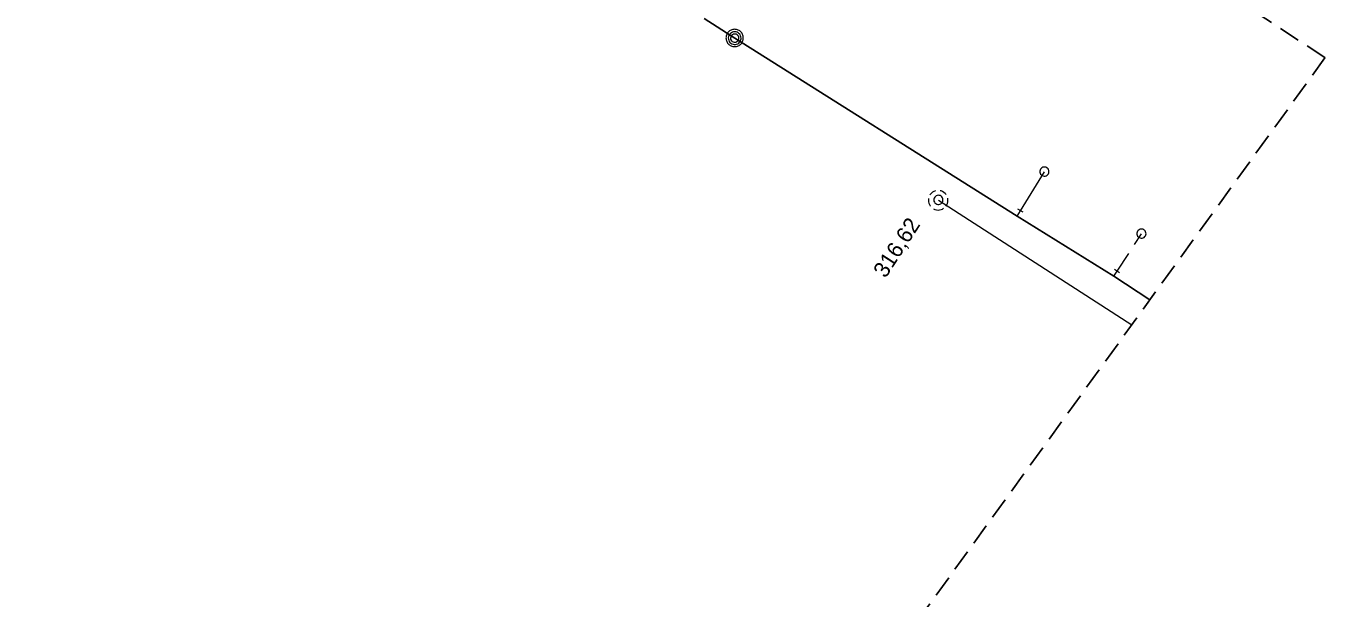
# Model space of a CAD drawing. Extents: x -742876 to -742577, y -1054710 to -1054452.
# Drawn here: x -742642.5 to -742577, y -1054581.2 to -1054552.3 of the extents above; entities that cross this region are included whole.
import ezdxf

# ---------------------------------------------------------------- set-up
doc = ezdxf.new("R2010")
doc.units = 0
doc.header["$LTSCALE"] = 0.36
doc.linetypes.add('MEDIUM_DASHED', pattern=[4.5, 3, -1.5])
for name, color, linetype, lineweight in [('1', 7, 'MEDIUM_DASHED', 25), ('18', 7, 'Continuous', 13), ('20', 7, 'Continuous', 13), ('8', 7, 'Continuous', 13)]:
    doc.layers.add(name, color=color, linetype=linetype, lineweight=lineweight)

msp = doc.modelspace()

# ---------------------------------------------------------------- linework, layer by layer
at = {"layer": '1'}
msp.add_lwpolyline([(-742732.306, -1054452.031), (-742576.984, -1054553.898), (-742576.983, -1054553.899), (-742576.982, -1054553.901), (-742576.981, -1054553.903), (-742576.98, -1054553.905), (-742576.98, -1054553.907), (-742576.98, -1054553.909), (-742576.981, -1054553.91), (-742576.982, -1054553.912), (-742690.097, -1054710.32), (-742690.098, -1054710.321), (-742690.099, -1054710.322), (-742690.101, -1054710.323), (-742690.103, -1054710.324), (-742690.105, -1054710.324), (-742690.107, -1054710.324), (-742690.108, -1054710.323), (-742690.11, -1054710.322), (-742875.986, -1054593.411)], dxfattribs=at)
at = {"layer": '18'}
for points in [[(-742596.642, -1054560.627), (-742596.713, -1054560.655), (-742596.779, -1054560.694), (-742596.84, -1054560.742), (-742596.891, -1054560.799), (-742596.914, -1054560.833)], [(-742596.1, -1054560.81), (-742596.151, -1054560.752), (-742596.208, -1054560.702), (-742596.274, -1054560.661), (-742596.345, -1054560.632), (-742596.394, -1054560.618)], [(-742596.987, -1054561.019), (-742596.992, -1054561.096), (-742596.987, -1054561.173), (-742596.97, -1054561.248), (-742596.941, -1054561.319), (-742596.901, -1054561.385), (-742596.886, -1054561.407)], [(-742596.105, -1054561.396), (-742596.065, -1054561.331), (-742596.034, -1054561.261), (-742596.014, -1054561.186), (-742596.007, -1054561.11), (-742596.012, -1054561.033), (-742596.017, -1054560.998)], [(-742596.728, -1054561.536), (-742596.659, -1054561.567), (-742596.583, -1054561.586), (-742596.507, -1054561.593), (-742596.431, -1054561.588), (-742596.355, -1054561.571), (-742596.284, -1054561.543), (-742596.223, -1054561.508)]]:
    msp.add_lwpolyline(points, dxfattribs=at)
msp.add_lwpolyline([(-742596.257, -1054561.079), (-742596.264, -1054561.027), (-742596.281, -1054560.977), (-742596.309, -1054560.933), (-742596.348, -1054560.896), (-742596.392, -1054560.869), (-742596.443, -1054560.853), (-742596.495, -1054560.848), (-742596.546, -1054560.855), (-742596.595, -1054560.874), (-742596.639, -1054560.904), (-742596.674, -1054560.943), (-742596.701, -1054560.988), (-742596.715, -1054561.039), (-742596.718, -1054561.091), (-742596.71, -1054561.143), (-742596.69, -1054561.191), (-742596.659, -1054561.234), (-742596.62, -1054561.269), (-742596.573, -1054561.293), (-742596.522, -1054561.307), (-742596.47, -1054561.309), (-742596.419, -1054561.299), (-742596.37, -1054561.277), (-742596.328, -1054561.245), (-742596.296, -1054561.205), (-742596.272, -1054561.158), (-742596.259, -1054561.107)], close=True, dxfattribs=at)
at = {"layer": '20'}
msp.add_line((-742596.489, -1054561.09), (-742586.729, -1054567.39), dxfattribs=at)
msp.add_line((-742596.489, -1054561.09), (-742586.729, -1054567.39), dxfattribs=at)
at = {"layer": '8', "lineweight": 25}
msp.add_line((-742608.309, -1054551.919), (-742606.761, -1054552.922), dxfattribs=at)
at = {"layer": '8'}
for p, q in [((-742592.217, -1054561.706), (-742592.473, -1054561.544)), ((-742587.353, -1054564.766), (-742587.607, -1054564.6))]:
    msp.add_line(p, q, dxfattribs=at)
for points in [[(-742606.33, -1054552.91), (-742606.332, -1054552.865), (-742606.339, -1054552.82), (-742606.351, -1054552.775), (-742606.367, -1054552.733), (-742606.388, -1054552.692), (-742606.413, -1054552.653), (-742606.442, -1054552.618), (-742606.474, -1054552.585), (-742606.51, -1054552.557), (-742606.548, -1054552.532), (-742606.589, -1054552.511), (-742606.632, -1054552.494), (-742606.676, -1054552.482), (-742606.721, -1054552.475), (-742606.767, -1054552.473), (-742606.813, -1054552.475), (-742606.858, -1054552.482), (-742606.902, -1054552.494), (-742606.945, -1054552.511), (-742606.986, -1054552.532), (-742607.024, -1054552.557), (-742607.06, -1054552.585), (-742607.092, -1054552.618), (-742607.121, -1054552.653), (-742607.146, -1054552.692), (-742607.167, -1054552.733), (-742607.183, -1054552.775), (-742607.195, -1054552.82), (-742607.202, -1054552.865), (-742607.205, -1054552.911), (-742607.202, -1054552.956), (-742607.195, -1054553.001), (-742607.183, -1054553.046), (-742607.167, -1054553.088), (-742607.146, -1054553.129), (-742607.121, -1054553.168), (-742607.092, -1054553.203), (-742607.06, -1054553.236), (-742607.024, -1054553.264), (-742606.986, -1054553.289), (-742606.945, -1054553.31), (-742606.902, -1054553.327), (-742606.858, -1054553.338), (-742606.813, -1054553.346), (-742606.767, -1054553.348), (-742606.721, -1054553.346), (-742606.676, -1054553.338), (-742606.632, -1054553.327), (-742606.589, -1054553.31), (-742606.548, -1054553.289), (-742606.51, -1054553.264), (-742606.474, -1054553.236), (-742606.442, -1054553.203), (-742606.413, -1054553.168), (-742606.388, -1054553.129), (-742606.367, -1054553.088), (-742606.351, -1054553.046), (-742606.339, -1054553.001), (-742606.332, -1054552.956), (-742606.33, -1054552.911)], [(-742592.51, -1054561.899), (-742592.34, -1054561.629), (-742591.131, -1054559.659)]]:
    msp.add_lwpolyline(points, dxfattribs=at)
for points in [[(-742606.443, -1054552.918), (-742606.449, -1054552.857), (-742606.467, -1054552.797), (-742606.496, -1054552.742), (-742606.535, -1054552.694), (-742606.582, -1054552.654), (-742606.636, -1054552.624), (-742606.695, -1054552.604), (-742606.757, -1054552.597), (-742606.819, -1054552.601), (-742606.879, -1054552.617), (-742606.934, -1054552.645), (-742606.984, -1054552.682), (-742607.025, -1054552.729), (-742607.057, -1054552.782), (-742607.077, -1054552.841), (-742607.087, -1054552.902), (-742607.084, -1054552.964), (-742607.069, -1054553.024), (-742607.043, -1054553.081), (-742607.007, -1054553.131), (-742606.961, -1054553.174), (-742606.909, -1054553.206), (-742606.851, -1054553.229), (-742606.79, -1054553.239), (-742606.728, -1054553.238), (-742606.667, -1054553.225), (-742606.61, -1054553.2), (-742606.559, -1054553.165), (-742606.515, -1054553.121), (-742606.481, -1054553.069), (-742606.457, -1054553.012), (-742606.445, -1054552.951)], [(-742606.557, -1054552.918), (-742606.563, -1054552.869), (-742606.58, -1054552.822), (-742606.608, -1054552.781), (-742606.646, -1054552.748), (-742606.69, -1054552.724), (-742606.738, -1054552.712), (-742606.788, -1054552.711), (-742606.836, -1054552.723), (-742606.881, -1054552.745), (-742606.919, -1054552.778), (-742606.948, -1054552.818), (-742606.967, -1054552.865), (-742606.974, -1054552.914), (-742606.969, -1054552.964), (-742606.952, -1054553.011), (-742606.925, -1054553.053), (-742606.888, -1054553.087), (-742606.845, -1054553.111), (-742606.797, -1054553.125), (-742606.747, -1054553.126), (-742606.698, -1054553.116), (-742606.653, -1054553.094), (-742606.614, -1054553.062), (-742606.584, -1054553.023), (-742606.565, -1054552.977), (-742606.557, -1054552.927)], [(-742591.015, -1054559.459), (-742591.062, -1054559.436), (-742591.114, -1054559.424), (-742591.166, -1054559.425), (-742591.218, -1054559.437), (-742591.265, -1054559.461), (-742591.305, -1054559.494), (-742591.337, -1054559.536), (-742591.359, -1054559.583), (-742591.369, -1054559.635), (-742591.367, -1054559.688), (-742591.353, -1054559.738), (-742591.329, -1054559.784), (-742591.293, -1054559.824), (-742591.251, -1054559.855), (-742591.203, -1054559.876), (-742591.151, -1054559.884), (-742591.099, -1054559.881), (-742591.048, -1054559.866), (-742591.003, -1054559.84), (-742590.964, -1054559.804), (-742590.934, -1054559.762), (-742590.915, -1054559.712), (-742590.908, -1054559.66), (-742590.913, -1054559.607), (-742590.929, -1054559.558), (-742590.956, -1054559.513), (-742590.992, -1054559.475)], [(-742586.115, -1054562.591), (-742586.162, -1054562.568), (-742586.213, -1054562.556), (-742586.265, -1054562.555), (-742586.317, -1054562.567), (-742586.364, -1054562.589), (-742586.405, -1054562.622), (-742586.438, -1054562.663), (-742586.46, -1054562.711), (-742586.471, -1054562.762), (-742586.47, -1054562.815), (-742586.457, -1054562.866), (-742586.434, -1054562.912), (-742586.399, -1054562.953), (-742586.357, -1054562.984), (-742586.309, -1054563.006), (-742586.258, -1054563.014), (-742586.205, -1054563.013), (-742586.154, -1054562.998), (-742586.109, -1054562.973), (-742586.069, -1054562.938), (-742586.039, -1054562.896), (-742586.019, -1054562.847), (-742586.011, -1054562.794), (-742586.015, -1054562.742), (-742586.03, -1054562.692), (-742586.056, -1054562.646), (-742586.092, -1054562.608)]]:
    msp.add_lwpolyline(points, close=True, dxfattribs=at)
at = {"layer": '8', "lineweight": 25}
msp.add_lwpolyline([(-742606.761, -1054552.922), (-742592.51, -1054561.899), (-742587.64, -1054564.94), (-742585.817, -1054566.13)], dxfattribs=at)
at = {"layer": '8', "linetype": 'MEDIUM_DASHED'}
msp.add_lwpolyline([(-742587.64, -1054564.94), (-742587.475, -1054564.688), (-742586.234, -1054562.791)], dxfattribs=at)

# ---------------------------------------------------------------- texts
at = {"layer": '1'}
msp.add_text('316,62', height=0.8, rotation=57, dxfattribs=at).set_placement((-742599.154, -1054565.069))

doc.saveas('drawing.dxf')
